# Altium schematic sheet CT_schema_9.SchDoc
size 387 x 278 mm
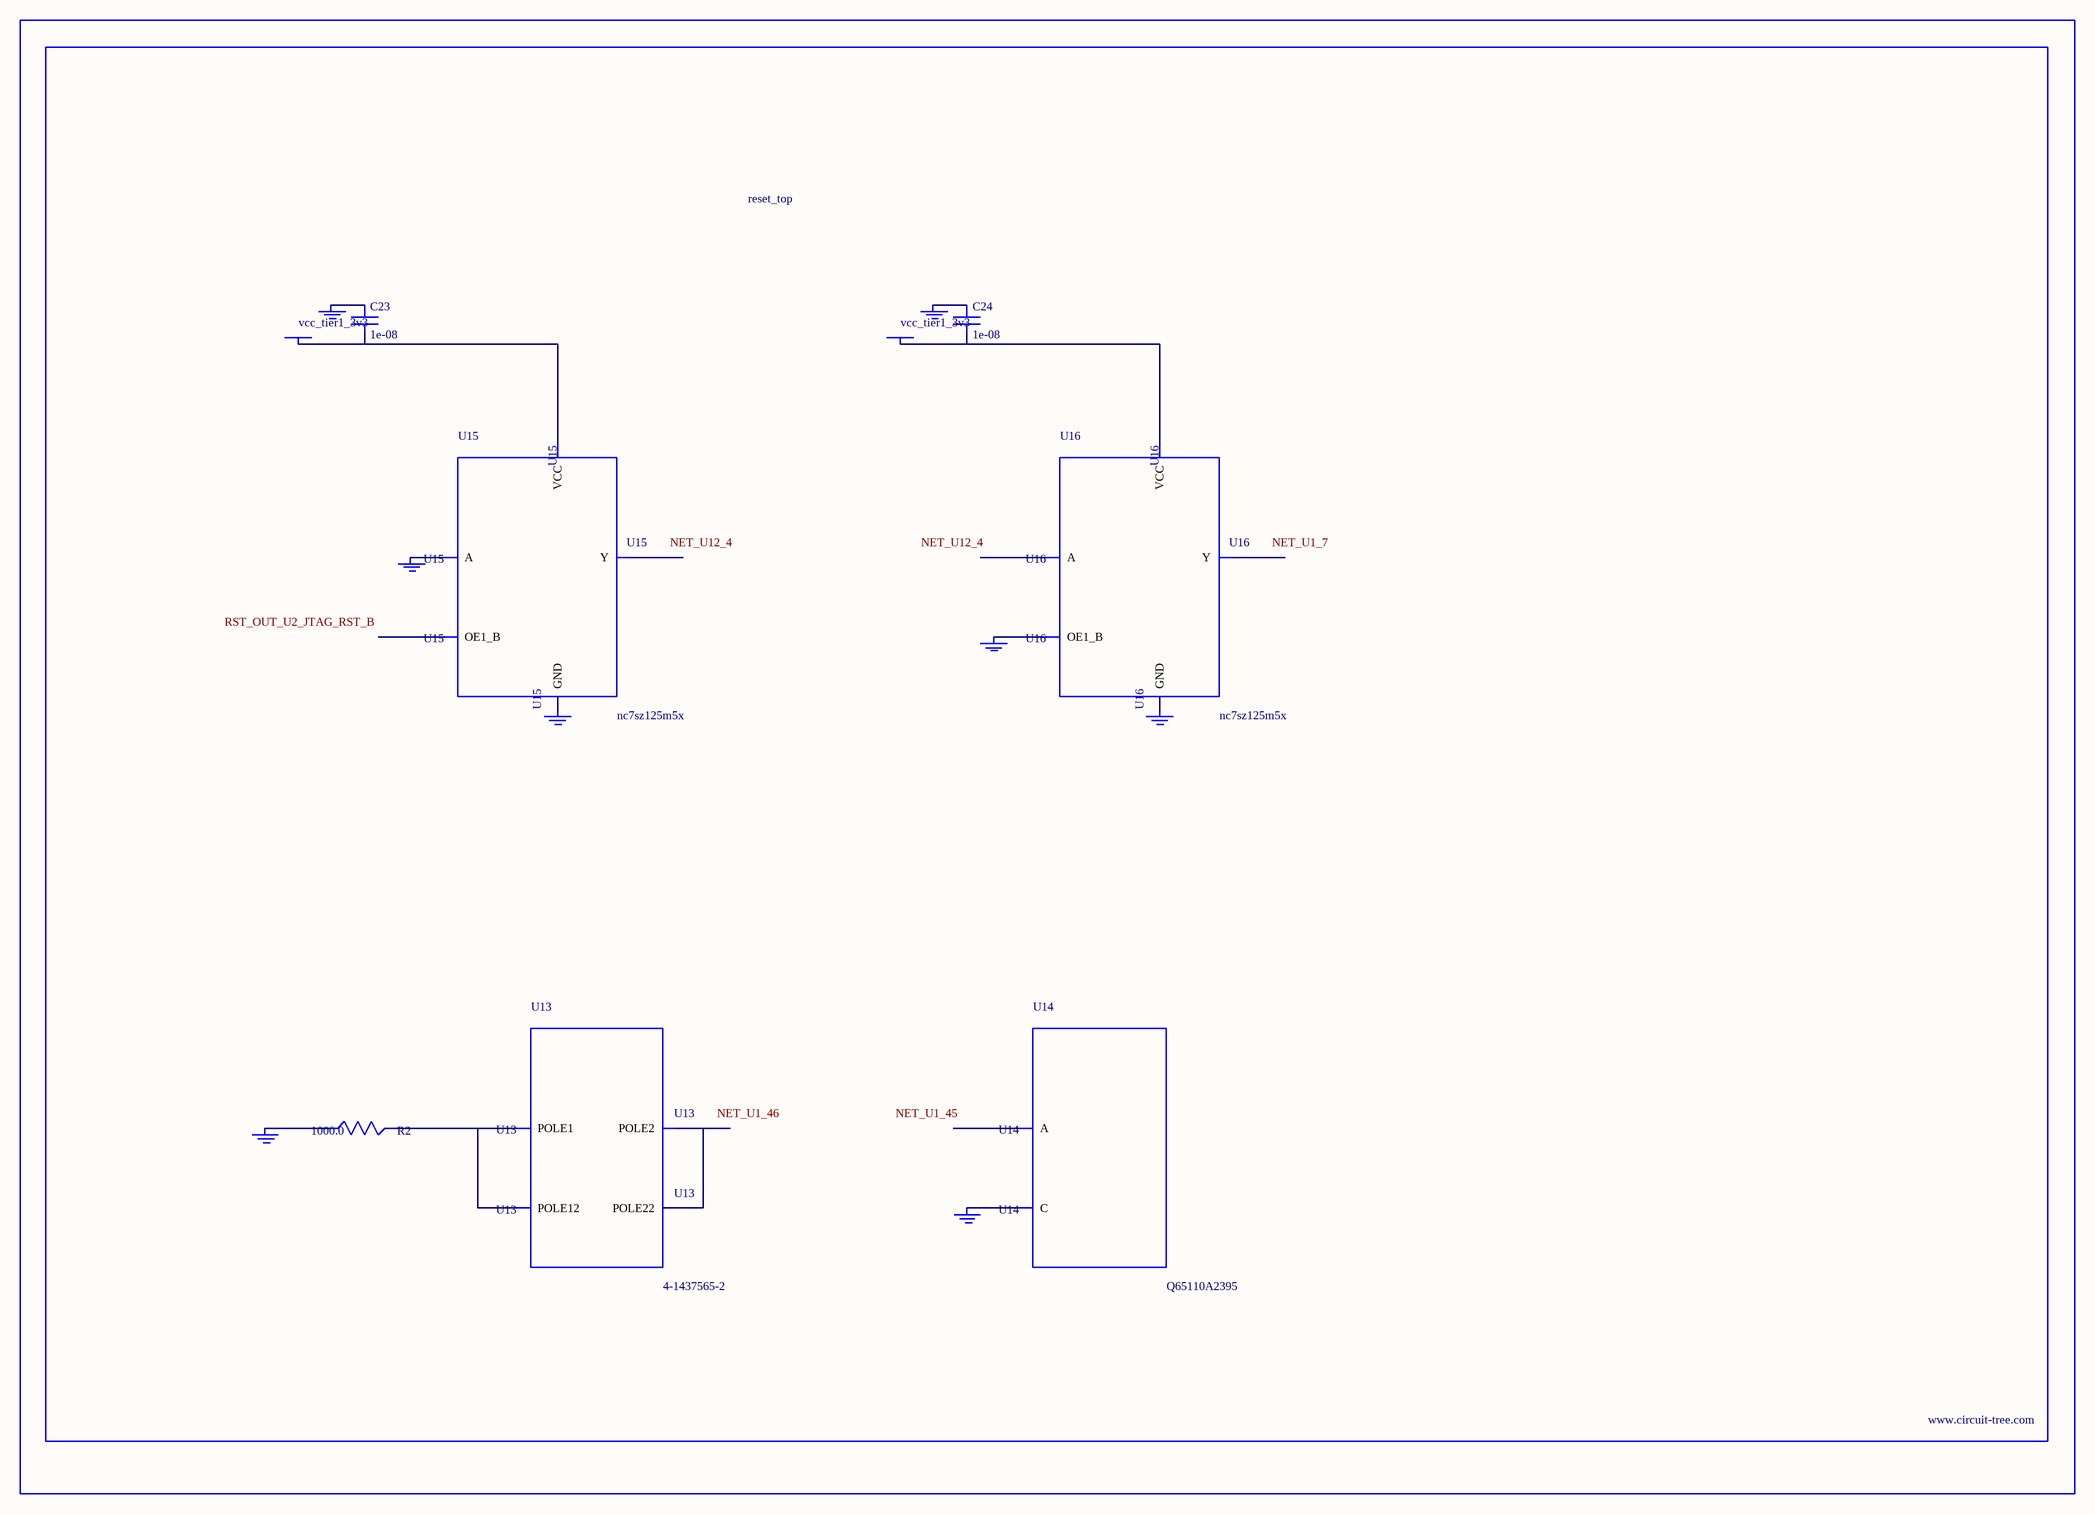
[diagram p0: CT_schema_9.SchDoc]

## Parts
BORDER8  (no value)
C23  1e-08  [C0402]
C24  1e-08  [C0402]
GND_INSTANCE_8_0  (no value)
GND_INSTANCE_8_1  (no value)
GND_INSTANCE_8_2  (no value)
GND_INSTANCE_8_3  (no value)
GND_INSTANCE_8_4  (no value)
GND_INSTANCE_8_5  (no value)
GND_INSTANCE_8_6  (no value)
GND_INSTANCE_8_7  (no value)
POWER_INSTANCE_8_0  vcc_tier1_3v3
POWER_INSTANCE_8_1  vcc_tier1_3v3
R2  1000.0  [R0603]
U13  4-1437565-2  [SW_4-1437565-2]
U14  Q65110A2395  [LGM67K-G1J2-24-Z]
U15  nc7sz125m5x  [NC7SZ125M5X]
U16  nc7sz125m5x  [NC7SZ125M5X]

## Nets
NetC23_1: C23.1 GND_INSTANCE_8_2.0(GND)
NetC23_2: C23.2 POWER_INSTANCE_8_0.0(PWR) U15.5(VCC)
NetC24_1: C24.1 GND_INSTANCE_8_5.0(GND)
NetC24_2: C24.2 POWER_INSTANCE_8_1.0(PWR) U16.5(VCC)
NetGND_INSTANCE_8_0_0: GND_INSTANCE_8_0.0(GND) R2.1
NetGND_INSTANCE_8_1_0: GND_INSTANCE_8_1.0(GND) U14.C
NetGND_INSTANCE_8_3_0: GND_INSTANCE_8_3.0(GND) U15.2(A)
NetGND_INSTANCE_8_4_0: GND_INSTANCE_8_4.0(GND) U15.3(GND)
NetGND_INSTANCE_8_6_0: GND_INSTANCE_8_6.0(GND) U16.1(OE1_B)
NetGND_INSTANCE_8_7_0: GND_INSTANCE_8_7.0(GND) U16.3(GND)
NetR2_2: R2.2 U13.1(POLE1) U13.2(POLE12)
NetU13_3: U13.3(POLE2) U13.4(POLE22)

Not connected (* = marked no-connect by the designer): U14 A; U15 1(OE1_B) 4(Y); U16 2(A) 4(Y)

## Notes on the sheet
- Labels drawn without touching a wire or pin: NET_U1_7, NET_U1_45, NET_U1_46, NET_U12_4, RST_OUT_U2_JTAG_RST_B

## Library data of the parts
BORDER8 = BORDER_PAGE8
C23 C24 = C0402C103K3RAC
GND_INSTANCE_8_0-GND_INSTANCE_8_7 = GND
POWER_INSTANCE_8_0 POWER_INSTANCE_8_1 = PWR
R2 = RC0603JR-071KL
